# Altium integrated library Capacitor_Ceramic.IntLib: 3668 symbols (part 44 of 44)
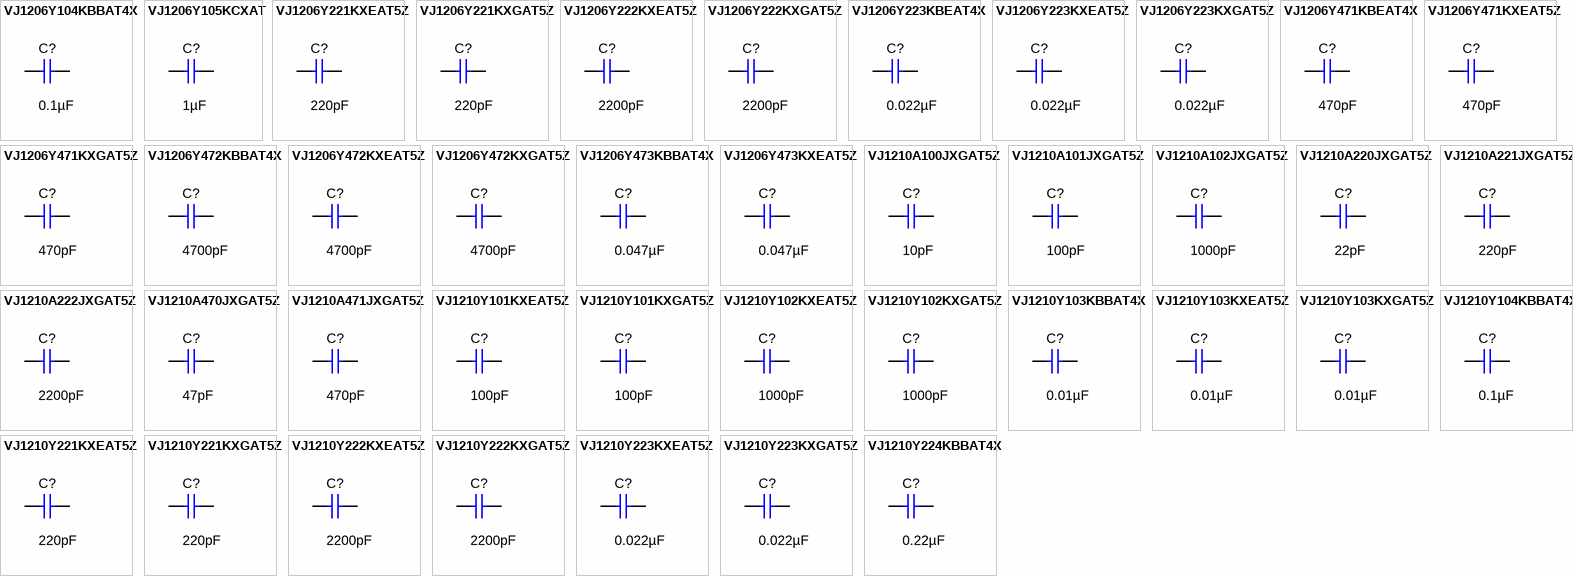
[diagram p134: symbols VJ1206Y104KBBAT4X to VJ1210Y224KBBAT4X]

## VJ1210Y104KBBAT4X
designator C?  ValueDisplayed: 0.1µF  (hidden comment: VJ1210Y104KBBAT4X)
CAP, CERM, 0.1 µF, 100 V,+/- 10%, X7R, 1210; Manufacturer: Vishay-Vitramon; Polarized: N; CompType: Capacitor; Value: 0.1uF; U/M: EA; Cap_F: 0.0000001; Tolerance_%: 10; VDC_V: 100; Value2: 100V; TaMin_C: -55; TaMax_C: 125; Cap_Case: 1210; SizeArea_mm2: 8; SizeAreaWB_mm2: 14.7; SizeX_mm: 3.2; SizeY_mm: 2.5; SizeZ_mm: 1.35; AEC Category: Q200
signal-integrity model Cap
simulation model Cap
footprint 1210
footprint 1210M
footprint 1210L
pins: 1, 2

## VJ1210Y221KXEAT5Z
designator C?  ValueDisplayed: 220pF  (hidden comment: VJ1210Y221KXEAT5Z)
CAP, CERM, 220 pF, 500 V,+/- 10%, X7R, 1210; Manufacturer: Vishay-Vitramon; Polarized: N; CompType: Capacitor; Value: 220pF; U/M: EA; Cap_F: 0.00000000022; Tolerance_%: 10; VDC_V: 500; Value2: 500V; TaMin_C: -55; TaMax_C: 125; Cap_Case: 1210; SizeArea_mm2: 8; SizeAreaWB_mm2: 14.7; SizeX_mm: 3.2; SizeY_mm: 2.5; SizeZ_mm: 1.35; AEC Category: Q200
signal-integrity model Cap
simulation model Cap
footprint 1210
footprint 1210M
footprint 1210L
pins: 1, 2

## VJ1210Y221KXGAT5Z
designator C?  ValueDisplayed: 220pF  (hidden comment: VJ1210Y221KXGAT5Z)
CAP, CERM, 220 pF, 1000 V,+/- 10%, X7R, 1210; Manufacturer: Vishay-Vitramon; Polarized: N; CompType: Capacitor; Value: 220pF; U/M: EA; Cap_F: 0.00000000022; Tolerance_%: 10; VDC_V: 1000; Value2: 1000V; TaMin_C: -55; TaMax_C: 125; Cap_Case: 1210; SizeArea_mm2: 8; SizeAreaWB_mm2: 14.7; SizeX_mm: 3.2; SizeY_mm: 2.5; SizeZ_mm: 1.35; AEC Category: Q200
signal-integrity model Cap
simulation model Cap
footprint 1210
footprint 1210M
footprint 1210L
pins: 1, 2

## VJ1210Y222KXEAT5Z
designator C?  ValueDisplayed: 2200pF  (hidden comment: VJ1210Y222KXEAT5Z)
CAP, CERM, 2200 pF, 500 V,+/- 10%, X7R, 1210; Manufacturer: Vishay-Vitramon; Polarized: N; CompType: Capacitor; Value: 2200pF; U/M: EA; Cap_F: 0.0000000022; Tolerance_%: 10; VDC_V: 500; Value2: 500V; TaMin_C: -55; TaMax_C: 125; Cap_Case: 1210; SizeArea_mm2: 8; SizeAreaWB_mm2: 14.7; SizeX_mm: 3.2; SizeY_mm: 2.5; SizeZ_mm: 1.35; AEC Category: Q200
signal-integrity model Cap
simulation model Cap
footprint 1210
footprint 1210M
footprint 1210L
pins: 1, 2

## VJ1210Y222KXGAT5Z
designator C?  ValueDisplayed: 2200pF  (hidden comment: VJ1210Y222KXGAT5Z)
CAP, CERM, 2200 pF, 1000 V,+/- 10%, X7R, 1210; Manufacturer: Vishay-Vitramon; Polarized: N; CompType: Capacitor; Value: 2200pF; U/M: EA; Cap_F: 0.0000000022; Tolerance_%: 10; VDC_V: 1000; Value2: 1000V; TaMin_C: -55; TaMax_C: 125; Cap_Case: 1210; SizeArea_mm2: 8; SizeAreaWB_mm2: 14.7; SizeX_mm: 3.2; SizeY_mm: 2.5; SizeZ_mm: 1.35; AEC Category: Q200
signal-integrity model Cap
simulation model Cap
footprint 1210
footprint 1210M
footprint 1210L
pins: 1, 2

## VJ1210Y223KXEAT5Z
designator C?  ValueDisplayed: 0.022µF  (hidden comment: VJ1210Y223KXEAT5Z)
CAP, CERM, 0.022 µF, 500 V,+/- 10%, X7R, 1210; Manufacturer: Vishay-Vitramon; Polarized: N; CompType: Capacitor; Value: 0.022uF; U/M: EA; Cap_F: 0.000000022; Tolerance_%: 10; VDC_V: 500; Value2: 500V; TaMin_C: -55; TaMax_C: 125; Cap_Case: 1210; SizeArea_mm2: 8; SizeAreaWB_mm2: 14.7; SizeX_mm: 3.2; SizeY_mm: 2.5; SizeZ_mm: 1.35; AEC Category: Q200
signal-integrity model Cap
simulation model Cap
footprint 1210
footprint 1210M
footprint 1210L
pins: 1, 2

## VJ1210Y223KXGAT5Z
designator C?  ValueDisplayed: 0.022µF  (hidden comment: VJ1210Y223KXGAT5Z)
CAP, CERM, 0.022 µF, 1000 V,+/- 10%, X7R, 1210; Manufacturer: Vishay-Vitramon; Polarized: N; CompType: Capacitor; Value: 0.022uF; U/M: EA; Cap_F: 0.000000022; Tolerance_%: 10; VDC_V: 1000; Value2: 1000V; TaMin_C: -55; TaMax_C: 125; Cap_Case: 1210; SizeArea_mm2: 8; SizeAreaWB_mm2: 14.7; SizeX_mm: 3.2; SizeY_mm: 2.5; SizeZ_mm: 1.35; AEC Category: Q200
signal-integrity model Cap
simulation model Cap
footprint 1210
footprint 1210M
footprint 1210L
pins: 1, 2

## VJ1210Y224KBBAT4X
designator C?  ValueDisplayed: 0.22µF  (hidden comment: VJ1210Y224KBBAT4X)
CAP, CERM, 0.22 µF, 100 V,+/- 10%, X7R, 1210; Manufacturer: Vishay-Vitramon; Polarized: N; CompType: Capacitor; Value: 0.22uF; U/M: EA; Cap_F: 0.00000022; Tolerance_%: 10; VDC_V: 100; Value2: 100V; TaMin_C: -55; TaMax_C: 125; Cap_Case: 1210; SizeArea_mm2: 8; SizeAreaWB_mm2: 14.7; SizeX_mm: 3.2; SizeY_mm: 2.5; SizeZ_mm: 1.35; AEC Category: Q200
signal-integrity model Cap
simulation model Cap
footprint 1210
footprint 1210M
footprint 1210L
pins: 1, 2

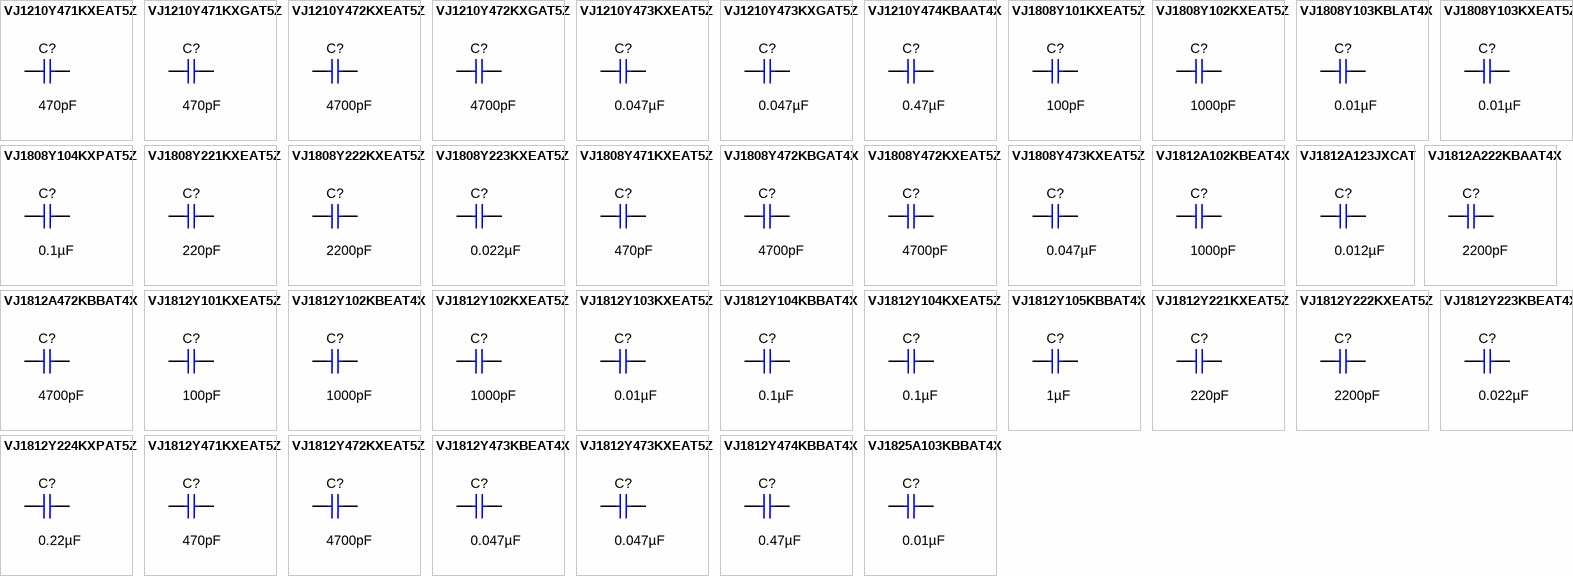
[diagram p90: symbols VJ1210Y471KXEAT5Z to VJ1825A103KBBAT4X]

## VJ1210Y471KXEAT5Z
designator C?  ValueDisplayed: 470pF  (hidden comment: VJ1210Y471KXEAT5Z)
CAP, CERM, 470 pF, 500 V,+/- 10%, X7R, 1210; Manufacturer: Vishay-Vitramon; Polarized: N; CompType: Capacitor; Value: 470pF; U/M: EA; Cap_F: 0.00000000047; Tolerance_%: 10; VDC_V: 500; Value2: 500V; TaMin_C: -55; TaMax_C: 125; Cap_Case: 1210; SizeArea_mm2: 8; SizeAreaWB_mm2: 14.7; SizeX_mm: 3.2; SizeY_mm: 2.5; SizeZ_mm: 1.35; AEC Category: Q200
signal-integrity model Cap
simulation model Cap
footprint 1210
footprint 1210M
footprint 1210L
pins: 1, 2

## VJ1210Y471KXGAT5Z
designator C?  ValueDisplayed: 470pF  (hidden comment: VJ1210Y471KXGAT5Z)
CAP, CERM, 470 pF, 1000 V,+/- 10%, X7R, 1210; Manufacturer: Vishay-Vitramon; Polarized: N; CompType: Capacitor; Value: 470pF; U/M: EA; Cap_F: 0.00000000047; Tolerance_%: 10; VDC_V: 1000; Value2: 1000V; TaMin_C: -55; TaMax_C: 125; Cap_Case: 1210; SizeArea_mm2: 8; SizeAreaWB_mm2: 14.7; SizeX_mm: 3.2; SizeY_mm: 2.5; SizeZ_mm: 1.35; AEC Category: Q200
signal-integrity model Cap
simulation model Cap
footprint 1210
footprint 1210M
footprint 1210L
pins: 1, 2

## VJ1210Y472KXEAT5Z
designator C?  ValueDisplayed: 4700pF  (hidden comment: VJ1210Y472KXEAT5Z)
CAP, CERM, 4700 pF, 500 V,+/- 10%, X7R, 1210; Manufacturer: Vishay-Vitramon; Polarized: N; CompType: Capacitor; Value: 4700pF; U/M: EA; Cap_F: 0.0000000047; Tolerance_%: 10; VDC_V: 500; Value2: 500V; TaMin_C: -55; TaMax_C: 125; Cap_Case: 1210; SizeArea_mm2: 8; SizeAreaWB_mm2: 14.7; SizeX_mm: 3.2; SizeY_mm: 2.5; SizeZ_mm: 1.35; AEC Category: Q200
signal-integrity model Cap
simulation model Cap
footprint 1210
footprint 1210M
footprint 1210L
pins: 1, 2

## VJ1210Y472KXGAT5Z
designator C?  ValueDisplayed: 4700pF  (hidden comment: VJ1210Y472KXGAT5Z)
CAP, CERM, 4700 pF, 1000 V,+/- 10%, X7R, 1210; Manufacturer: Vishay-Vitramon; Polarized: N; CompType: Capacitor; Value: 4700pF; U/M: EA; Cap_F: 0.0000000047; Tolerance_%: 10; VDC_V: 1000; Value2: 1000V; TaMin_C: -55; TaMax_C: 125; Cap_Case: 1210; SizeArea_mm2: 8; SizeAreaWB_mm2: 14.7; SizeX_mm: 3.2; SizeY_mm: 2.5; SizeZ_mm: 1.35; AEC Category: Q200
signal-integrity model Cap
simulation model Cap
footprint 1210
footprint 1210M
footprint 1210L
pins: 1, 2

## VJ1210Y473KXEAT5Z
designator C?  ValueDisplayed: 0.047µF  (hidden comment: VJ1210Y473KXEAT5Z)
CAP, CERM, 0.047 µF, 500 V,+/- 10%, X7R, 1210; Manufacturer: Vishay-Vitramon; Polarized: N; CompType: Capacitor; Value: 0.047uF; U/M: EA; Cap_F: 0.000000047; Tolerance_%: 10; VDC_V: 500; Value2: 500V; TaMin_C: -55; TaMax_C: 125; Cap_Case: 1210; SizeArea_mm2: 8; SizeAreaWB_mm2: 14.7; SizeX_mm: 3.2; SizeY_mm: 2.5; SizeZ_mm: 1.35; AEC Category: Q200
signal-integrity model Cap
simulation model Cap
footprint 1210
footprint 1210M
footprint 1210L
pins: 1, 2

## VJ1210Y473KXGAT5Z
designator C?  ValueDisplayed: 0.047µF  (hidden comment: VJ1210Y473KXGAT5Z)
CAP, CERM, 0.047 µF, 1000 V,+/- 10%, X7R, 1210; Manufacturer: Vishay-Vitramon; Polarized: N; CompType: Capacitor; Value: 0.047uF; U/M: EA; Cap_F: 0.000000047; Tolerance_%: 10; VDC_V: 1000; Value2: 1000V; TaMin_C: -55; TaMax_C: 125; Cap_Case: 1210; SizeArea_mm2: 8; SizeAreaWB_mm2: 14.7; SizeX_mm: 3.2; SizeY_mm: 2.5; SizeZ_mm: 1.35; AEC Category: Q200
signal-integrity model Cap
simulation model Cap
footprint 1210
footprint 1210M
footprint 1210L
pins: 1, 2

## VJ1210Y474KBAAT4X
designator C?  ValueDisplayed: 0.47µF  (hidden comment: VJ1210Y474KBAAT4X)
CAP, CERM, 0.47 µF, 50 V,+/- 10%, X7R, 1210; Manufacturer: Vishay-Vitramon; Polarized: N; CompType: Capacitor; Value: 0.47uF; U/M: EA; Cap_F: 0.00000047; Tolerance_%: 10; VDC_V: 50; Value2: 50V; TaMin_C: -55; TaMax_C: 125; Cap_Case: 1210; SizeArea_mm2: 8; SizeAreaWB_mm2: 14.7; SizeX_mm: 3.2; SizeY_mm: 2.5; SizeZ_mm: 1.35; AEC Category: Q200
signal-integrity model Cap
simulation model Cap
footprint 1210
footprint 1210M
footprint 1210L
pins: 1, 2

## VJ1808Y101KXEAT5Z
designator C?  ValueDisplayed: 100pF  (hidden comment: VJ1808Y101KXEAT5Z)
CAP, CERM, 100 pF, 500 V,+/- 10%, X7R, 1808; Manufacturer: Vishay-Vitramon; Polarized: N; CompType: Capacitor; Value: 100pF; U/M: EA; Cap_F: 0.0000000001; Tolerance_%: 10; VDC_V: 500; Value2: 500V; TaMin_C: -55; TaMax_C: 125; Cap_Case: 1808; SizeArea_mm2: 9; SizeAreaWB_mm2: 16.5; SizeX_mm: 4.5; SizeY_mm: 2; SizeZ_mm: 2.03; AEC Category: Q200
signal-integrity model Cap
simulation model Cap
footprint 1808
footprint 1808_M
footprint 1808_L
pins: 1, 2

## VJ1808Y102KXEAT5Z
designator C?  ValueDisplayed: 1000pF  (hidden comment: VJ1808Y102KXEAT5Z)
CAP, CERM, 1000 pF, 500 V,+/- 10%, X7R, 1808; Manufacturer: Vishay-Vitramon; Polarized: N; CompType: Capacitor; Value: 1000pF; U/M: EA; Cap_F: 0.000000001; Tolerance_%: 10; VDC_V: 500; Value2: 500V; TaMin_C: -55; TaMax_C: 125; Cap_Case: 1808; SizeArea_mm2: 9; SizeAreaWB_mm2: 16.5; SizeX_mm: 4.5; SizeY_mm: 2; SizeZ_mm: 2.03; AEC Category: Q200
signal-integrity model Cap
simulation model Cap
footprint 1808
footprint 1808_M
footprint 1808_L
pins: 1, 2

## VJ1808Y103KBLAT4X
designator C?  ValueDisplayed: 0.01µF  (hidden comment: VJ1808Y103KBLAT4X)
CAP, CERM, 0.01 µF, 630 V,+/- 10%, X7R, 1808; Manufacturer: Vishay-Vitramon; Polarized: N; CompType: Capacitor; Value: 0.01uF; U/M: EA; Cap_F: 0.00000001; Tolerance_%: 10; VDC_V: 630; Value2: 630V; TaMin_C: -55; TaMax_C: 125; Cap_Case: 1808; SizeArea_mm2: 9; SizeAreaWB_mm2: 16.5; SizeX_mm: 4.5; SizeY_mm: 2; SizeZ_mm: 2.03; AEC Category: Q200
signal-integrity model Cap
simulation model Cap
footprint 1808
footprint 1808_M
footprint 1808_L
pins: 1, 2

## VJ1808Y103KXEAT5Z
designator C?  ValueDisplayed: 0.01µF  (hidden comment: VJ1808Y103KXEAT5Z)
CAP, CERM, 0.01 µF, 500 V,+/- 10%, X7R, 1808; Manufacturer: Vishay-Vitramon; Polarized: N; CompType: Capacitor; Value: 0.01uF; U/M: EA; Cap_F: 0.00000001; Tolerance_%: 10; VDC_V: 500; Value2: 500V; TaMin_C: -55; TaMax_C: 125; Cap_Case: 1808; SizeArea_mm2: 9; SizeAreaWB_mm2: 16.5; SizeX_mm: 4.5; SizeY_mm: 2; SizeZ_mm: 2.03; AEC Category: Q200
signal-integrity model Cap
simulation model Cap
footprint 1808
footprint 1808_M
footprint 1808_L
pins: 1, 2

## VJ1808Y104KXPAT5Z
designator C?  ValueDisplayed: 0.1µF  (hidden comment: VJ1808Y104KXPAT5Z)
CAP, CERM, 0.1 µF, 250 V,+/- 10%, X7R, 1808; Manufacturer: Vishay-Vitramon; Polarized: N; CompType: Capacitor; Value: 0.1uF; U/M: EA; Cap_F: 0.0000001; Tolerance_%: 10; VDC_V: 250; Value2: 250V; TaMin_C: -55; TaMax_C: 125; Cap_Case: 1808; SizeArea_mm2: 9; SizeAreaWB_mm2: 16.5; SizeX_mm: 4.5; SizeY_mm: 2; SizeZ_mm: 2.03; AEC Category: Q200
signal-integrity model Cap
simulation model Cap
footprint 1808
footprint 1808_M
footprint 1808_L
pins: 1, 2

## VJ1808Y221KXEAT5Z
designator C?  ValueDisplayed: 220pF  (hidden comment: VJ1808Y221KXEAT5Z)
CAP, CERM, 220 pF, 500 V,+/- 10%, X7R, 1808; Manufacturer: Vishay-Vitramon; Polarized: N; CompType: Capacitor; Value: 220pF; U/M: EA; Cap_F: 0.00000000022; Tolerance_%: 10; VDC_V: 500; Value2: 500V; TaMin_C: -55; TaMax_C: 125; Cap_Case: 1808; SizeArea_mm2: 9; SizeAreaWB_mm2: 16.5; SizeX_mm: 4.5; SizeY_mm: 2; SizeZ_mm: 2.03; AEC Category: Q200
signal-integrity model Cap
simulation model Cap
footprint 1808
footprint 1808_M
footprint 1808_L
pins: 1, 2

## VJ1808Y222KXEAT5Z
designator C?  ValueDisplayed: 2200pF  (hidden comment: VJ1808Y222KXEAT5Z)
CAP, CERM, 2200 pF, 500 V,+/- 10%, X7R, 1808; Manufacturer: Vishay-Vitramon; Polarized: N; CompType: Capacitor; Value: 2200pF; U/M: EA; Cap_F: 0.0000000022; Tolerance_%: 10; VDC_V: 500; Value2: 500V; TaMin_C: -55; TaMax_C: 125; Cap_Case: 1808; SizeArea_mm2: 9; SizeAreaWB_mm2: 16.5; SizeX_mm: 4.5; SizeY_mm: 2; SizeZ_mm: 2.03; AEC Category: Q200
signal-integrity model Cap
simulation model Cap
footprint 1808
footprint 1808_M
footprint 1808_L
pins: 1, 2

## VJ1808Y223KXEAT5Z
designator C?  ValueDisplayed: 0.022µF  (hidden comment: VJ1808Y223KXEAT5Z)
CAP, CERM, 0.022 µF, 500 V,+/- 10%, X7R, 1808; Manufacturer: Vishay-Vitramon; Polarized: N; CompType: Capacitor; Value: 0.022uF; U/M: EA; Cap_F: 0.000000022; Tolerance_%: 10; VDC_V: 500; Value2: 500V; TaMin_C: -55; TaMax_C: 125; Cap_Case: 1808; SizeArea_mm2: 9; SizeAreaWB_mm2: 16.5; SizeX_mm: 4.5; SizeY_mm: 2; SizeZ_mm: 2.03; AEC Category: Q200
signal-integrity model Cap
simulation model Cap
footprint 1808
footprint 1808_M
footprint 1808_L
pins: 1, 2

## VJ1808Y471KXEAT5Z
designator C?  ValueDisplayed: 470pF  (hidden comment: VJ1808Y471KXEAT5Z)
CAP, CERM, 470 pF, 500 V,+/- 10%, X7R, 1808; Manufacturer: Vishay-Vitramon; Polarized: N; CompType: Capacitor; Value: 470pF; U/M: EA; Cap_F: 0.00000000047; Tolerance_%: 10; VDC_V: 500; Value2: 500V; TaMin_C: -55; TaMax_C: 125; Cap_Case: 1808; SizeArea_mm2: 9; SizeAreaWB_mm2: 16.5; SizeX_mm: 4.5; SizeY_mm: 2; SizeZ_mm: 2.03; AEC Category: Q200
signal-integrity model Cap
simulation model Cap
footprint 1808
footprint 1808_M
footprint 1808_L
pins: 1, 2

## VJ1808Y472KBGAT4X
designator C?  ValueDisplayed: 4700pF  (hidden comment: VJ1808Y472KBGAT4X)
CAP, CERM, 4700 pF, 1000 V,+/- 10%, X7R, 1808; Manufacturer: Vishay-Vitramon; Polarized: N; CompType: Capacitor; Value: 4700pF; U/M: EA; Cap_F: 0.0000000047; Tolerance_%: 10; VDC_V: 1000; Value2: 1000V; TaMin_C: -55; TaMax_C: 125; Cap_Case: 1808; SizeArea_mm2: 9; SizeAreaWB_mm2: 16.5; SizeX_mm: 4.5; SizeY_mm: 2; SizeZ_mm: 2.03; AEC Category: Q200
signal-integrity model Cap
simulation model Cap
footprint 1808
footprint 1808_M
footprint 1808_L
pins: 1, 2

## VJ1808Y472KXEAT5Z
designator C?  ValueDisplayed: 4700pF  (hidden comment: VJ1808Y472KXEAT5Z)
CAP, CERM, 4700 pF, 500 V,+/- 10%, X7R, 1808; Manufacturer: Vishay-Vitramon; Polarized: N; CompType: Capacitor; Value: 4700pF; U/M: EA; Cap_F: 0.0000000047; Tolerance_%: 10; VDC_V: 500; Value2: 500V; TaMin_C: -55; TaMax_C: 125; Cap_Case: 1808; SizeArea_mm2: 9; SizeAreaWB_mm2: 16.5; SizeX_mm: 4.5; SizeY_mm: 2; SizeZ_mm: 2.03; AEC Category: Q200
signal-integrity model Cap
simulation model Cap
footprint 1808
footprint 1808_M
footprint 1808_L
pins: 1, 2

## VJ1808Y473KXEAT5Z
designator C?  ValueDisplayed: 0.047µF  (hidden comment: VJ1808Y473KXEAT5Z)
CAP, CERM, 0.047 µF, 500 V,+/- 10%, X7R, 1808; Manufacturer: Vishay-Vitramon; Polarized: N; CompType: Capacitor; Value: 0.047uF; U/M: EA; Cap_F: 0.000000047; Tolerance_%: 10; VDC_V: 500; Value2: 500V; TaMin_C: -55; TaMax_C: 125; Cap_Case: 1808; SizeArea_mm2: 9; SizeAreaWB_mm2: 16.5; SizeX_mm: 4.5; SizeY_mm: 2; SizeZ_mm: 2.03; AEC Category: Q200
signal-integrity model Cap
simulation model Cap
footprint 1808
footprint 1808_M
footprint 1808_L
pins: 1, 2

## VJ1812A102KBEAT4X
designator C?  ValueDisplayed: 1000pF  (hidden comment: VJ1812A102KBEAT4X)
CAP, CERM, 1000 pF, 500 V,+/- 10%, C0G/NP0, 1812; Manufacturer: Vishay-Vitramon; Polarized: N; CompType: Capacitor; Value: 1000pF; U/M: EA; Cap_F: 0.000000001; Tolerance_%: 10; VDC_V: 500; Value2: 500V; TaMin_C: -55; TaMax_C: 125; Cap_Case: 1812; SizeArea_mm2: 14.4; SizeAreaWB_mm2: 23.1; SizeX_mm: 4.5; SizeY_mm: 3.2; SizeZ_mm: 1.35; AEC Category: Q200
signal-integrity model Cap
simulation model Cap
footprint 1812
footprint 1812M
footprint 1812L
footprint 1812_HV
pins: 1, 2

## VJ1812A123JXCAT
designator C?  ValueDisplayed: 0.012µF  (hidden comment: VJ1812A123JXCAT)
CAP, CERM, 0.012 µF, 200 V,+/- 5%, C0G/NP0, 1812; Manufacturer: Vishay-Vitramon; Polarized: N; CompType: Capacitor; Value: 0.012uF; U/M: EA; Cap_F: 0.000000012; Tolerance_%: 5; VDC_V: 200; Value2: 200V; TaMin_C: -55; TaMax_C: 125; Cap_Case: 1812; SizeArea_mm2: 14.4; SizeAreaWB_mm2: 23.1; SizeX_mm: 4.5; SizeY_mm: 3.2; SizeZ_mm: 2.54; AEC Category: Q200
signal-integrity model Cap
simulation model Cap
footprint 1812_254
pins: 1, 2

## VJ1812A222KBAAT4X
designator C?  ValueDisplayed: 2200pF  (hidden comment: VJ1812A222KBAAT4X)
CAP, CERM, 2200 pF, 50 V,+/- 10%, C0G/NP0, 1812; Manufacturer: Vishay-Vitramon; Polarized: N; CompType: Capacitor; Value: 2200pF; U/M: EA; Cap_F: 0.0000000022; Tolerance_%: 10; VDC_V: 50; Value2: 50V; TaMin_C: -55; TaMax_C: 125; Cap_Case: 1812; SizeArea_mm2: 14.4; SizeAreaWB_mm2: 23.1; SizeX_mm: 4.5; SizeY_mm: 3.2; SizeZ_mm: 1.35; AEC Category: Q200
signal-integrity model Cap
simulation model Cap
footprint 1812
footprint 1812M
footprint 1812L
footprint 1812_HV
pins: 1, 2

## VJ1812A472KBBAT4X
designator C?  ValueDisplayed: 4700pF  (hidden comment: VJ1812A472KBBAT4X)
CAP, CERM, 4700 pF, 100 V,+/- 10%, C0G/NP0, 1812; Manufacturer: Vishay-Vitramon; Polarized: N; CompType: Capacitor; Value: 4700pF; U/M: EA; Cap_F: 0.0000000047; Tolerance_%: 10; VDC_V: 100; Value2: 100V; TaMin_C: -55; TaMax_C: 125; Cap_Case: 1812; SizeArea_mm2: 14.4; SizeAreaWB_mm2: 23.1; SizeX_mm: 4.5; SizeY_mm: 3.2; SizeZ_mm: 1.35; AEC Category: Q200
signal-integrity model Cap
simulation model Cap
footprint 1812
footprint 1812M
footprint 1812L
footprint 1812_HV
pins: 1, 2

## VJ1812Y101KXEAT5Z
designator C?  ValueDisplayed: 100pF  (hidden comment: VJ1812Y101KXEAT5Z)
CAP, CERM, 100 pF, 500 V,+/- 10%, X7R, 1812; Manufacturer: Vishay-Vitramon; Polarized: N; CompType: Capacitor; Value: 100pF; U/M: EA; Cap_F: 0.0000000001; Tolerance_%: 10; VDC_V: 500; Value2: 500V; TaMin_C: -55; TaMax_C: 125; Cap_Case: 1812; SizeArea_mm2: 14.4; SizeAreaWB_mm2: 23.1; SizeX_mm: 4.5; SizeY_mm: 3.2; SizeZ_mm: 1.35; AEC Category: Q200
signal-integrity model Cap
simulation model Cap
footprint 1812
footprint 1812M
footprint 1812L
footprint 1812_HV
pins: 1, 2

## VJ1812Y102KBEAT4X
designator C?  ValueDisplayed: 1000pF  (hidden comment: VJ1812Y102KBEAT4X)
CAP, CERM, 1000 pF, 500 V,+/- 10%, X7R, 1812; Manufacturer: Vishay-Vitramon; Polarized: N; CompType: Capacitor; Value: 1000pF; U/M: EA; Cap_F: 0.000000001; Tolerance_%: 10; VDC_V: 500; Value2: 500V; TaMin_C: -55; TaMax_C: 125; Cap_Case: 1812; SizeArea_mm2: 14.4; SizeAreaWB_mm2: 23.1; SizeX_mm: 4.5; SizeY_mm: 3.2; SizeZ_mm: 1.35; AEC Category: Q200
signal-integrity model Cap
simulation model Cap
footprint 1812
footprint 1812M
footprint 1812L
footprint 1812_HV
pins: 1, 2

## VJ1812Y102KXEAT5Z
designator C?  ValueDisplayed: 1000pF  (hidden comment: VJ1812Y102KXEAT5Z)
CAP, CERM, 1000 pF, 500 V,+/- 10%, X7R, 1812; Manufacturer: Vishay-Vitramon; Polarized: N; CompType: Capacitor; Value: 1000pF; U/M: EA; Cap_F: 0.000000001; Tolerance_%: 10; VDC_V: 500; Value2: 500V; TaMin_C: -55; TaMax_C: 125; Cap_Case: 1812; SizeArea_mm2: 14.4; SizeAreaWB_mm2: 23.1; SizeX_mm: 4.5; SizeY_mm: 3.2; SizeZ_mm: 1.35; AEC Category: Q200
signal-integrity model Cap
simulation model Cap
footprint 1812
footprint 1812M
footprint 1812L
footprint 1812_HV
pins: 1, 2

## VJ1812Y103KXEAT5Z
designator C?  ValueDisplayed: 0.01µF  (hidden comment: VJ1812Y103KXEAT5Z)
CAP, CERM, 0.01 µF, 500 V,+/- 10%, X7R, 1812; Manufacturer: Vishay-Vitramon; Polarized: N; CompType: Capacitor; Value: 0.01uF; U/M: EA; Cap_F: 0.00000001; Tolerance_%: 10; VDC_V: 500; Value2: 500V; TaMin_C: -55; TaMax_C: 125; Cap_Case: 1812; SizeArea_mm2: 14.4; SizeAreaWB_mm2: 23.1; SizeX_mm: 4.5; SizeY_mm: 3.2; SizeZ_mm: 1.35; AEC Category: Q200
signal-integrity model Cap
simulation model Cap
footprint 1812
footprint 1812M
footprint 1812L
footprint 1812_HV
pins: 1, 2

## VJ1812Y104KBBAT4X
designator C?  ValueDisplayed: 0.1µF  (hidden comment: VJ1812Y104KBBAT4X)
CAP, CERM, 0.1 µF, 100 V,+/- 10%, X7R, 1812; Manufacturer: Vishay-Vitramon; Polarized: N; CompType: Capacitor; Value: 0.1uF; U/M: EA; Cap_F: 0.0000001; Tolerance_%: 10; VDC_V: 100; Value2: 100V; TaMin_C: -55; TaMax_C: 125; Cap_Case: 1812; SizeArea_mm2: 14.4; SizeAreaWB_mm2: 23.1; SizeX_mm: 4.5; SizeY_mm: 3.2; SizeZ_mm: 1.35; AEC Category: Q200
signal-integrity model Cap
simulation model Cap
footprint 1812
footprint 1812M
footprint 1812L
footprint 1812_HV
pins: 1, 2

## VJ1812Y104KXEAT5Z
designator C?  ValueDisplayed: 0.1µF  (hidden comment: VJ1812Y104KXEAT5Z)
CAP, CERM, 0.1 µF, 500 V,+/- 10%, X7R, 1812; Manufacturer: Vishay-Vitramon; Polarized: N; CompType: Capacitor; Value: 0.1uF; U/M: EA; Cap_F: 0.0000001; Tolerance_%: 10; VDC_V: 500; Value2: 500V; TaMin_C: -55; TaMax_C: 125; Cap_Case: 1812; SizeArea_mm2: 14.4; SizeAreaWB_mm2: 23.1; SizeX_mm: 4.5; SizeY_mm: 3.2; SizeZ_mm: 1.35; AEC Category: Q200
signal-integrity model Cap
simulation model Cap
footprint 1812
footprint 1812M
footprint 1812L
footprint 1812_HV
pins: 1, 2

## VJ1812Y105KBBAT4X
designator C?  ValueDisplayed: 1µF  (hidden comment: VJ1812Y105KBBAT4X)
CAP, CERM, 1 µF, 100 V,+/- 10%, X7R, 1812; Manufacturer: Vishay-Vitramon; Polarized: N; CompType: Capacitor; Value: 1uF; U/M: EA; Cap_F: 0.000001; Tolerance_%: 10; VDC_V: 100; Value2: 100V; TaMin_C: -55; TaMax_C: 125; Cap_Case: 1812; SizeArea_mm2: 14.4; SizeAreaWB_mm2: 23.1; SizeX_mm: 4.5; SizeY_mm: 3.2; SizeZ_mm: 1.35; AEC Category: Q200
signal-integrity model Cap
simulation model Cap
footprint 1812
footprint 1812M
footprint 1812L
footprint 1812_HV
pins: 1, 2

## VJ1812Y221KXEAT5Z
designator C?  ValueDisplayed: 220pF  (hidden comment: VJ1812Y221KXEAT5Z)
CAP, CERM, 220 pF, 500 V,+/- 10%, X7R, 1812; Manufacturer: Vishay-Vitramon; Polarized: N; CompType: Capacitor; Value: 220pF; U/M: EA; Cap_F: 0.00000000022; Tolerance_%: 10; VDC_V: 500; Value2: 500V; TaMin_C: -55; TaMax_C: 125; Cap_Case: 1812; SizeArea_mm2: 14.4; SizeAreaWB_mm2: 23.1; SizeX_mm: 4.5; SizeY_mm: 3.2; SizeZ_mm: 1.35; AEC Category: Q200
signal-integrity model Cap
simulation model Cap
footprint 1812
footprint 1812M
footprint 1812L
footprint 1812_HV
pins: 1, 2

## VJ1812Y222KXEAT5Z
designator C?  ValueDisplayed: 2200pF  (hidden comment: VJ1812Y222KXEAT5Z)
CAP, CERM, 2200 pF, 500 V,+/- 10%, X7R, 1812; Manufacturer: Vishay-Vitramon; Polarized: N; CompType: Capacitor; Value: 2200pF; U/M: EA; Cap_F: 0.0000000022; Tolerance_%: 10; VDC_V: 500; Value2: 500V; TaMin_C: -55; TaMax_C: 125; Cap_Case: 1812; SizeArea_mm2: 14.4; SizeAreaWB_mm2: 23.1; SizeX_mm: 4.5; SizeY_mm: 3.2; SizeZ_mm: 1.35; AEC Category: Q200
signal-integrity model Cap
simulation model Cap
footprint 1812
footprint 1812M
footprint 1812L
footprint 1812_HV
pins: 1, 2

## VJ1812Y223KBEAT4X
designator C?  ValueDisplayed: 0.022µF  (hidden comment: VJ1812Y223KBEAT4X)
CAP, CERM, 0.022 µF, 500 V,+/- 10%, X7R, 1812; Manufacturer: Vishay-Vitramon; Polarized: N; CompType: Capacitor; Value: 0.022uF; U/M: EA; Cap_F: 0.000000022; Tolerance_%: 10; VDC_V: 500; Value2: 500V; TaMin_C: -55; TaMax_C: 125; Cap_Case: 1812; SizeArea_mm2: 14.4; SizeAreaWB_mm2: 23.1; SizeX_mm: 4.5; SizeY_mm: 3.2; SizeZ_mm: 1.35; AEC Category: Q200; Green_Lifecycle: Not Set; Green_REACh: Incomplete
signal-integrity model Cap
simulation model Cap
footprint 1812
footprint 1812M
footprint 1812L
footprint 1812_HV
pins: 1, 2

## VJ1812Y224KXPAT5Z
designator C?  ValueDisplayed: 0.22µF  (hidden comment: VJ1812Y224KXPAT5Z)
CAP, CERM, 0.22 µF, 250 V,+/- 10%, X7R, 1812; Manufacturer: Vishay-Vitramon; Polarized: N; CompType: Capacitor; Value: 0.22uF; U/M: EA; Cap_F: 0.00000022; Tolerance_%: 10; VDC_V: 250; Value2: 250V; TaMin_C: -55; TaMax_C: 125; Cap_Case: 1812; SizeArea_mm2: 14.4; SizeAreaWB_mm2: 23.1; SizeX_mm: 4.5; SizeY_mm: 3.2; SizeZ_mm: 1.35; AEC Category: Q200
signal-integrity model Cap
simulation model Cap
footprint 1812
footprint 1812M
footprint 1812L
footprint 1812_HV
pins: 1, 2

## VJ1812Y471KXEAT5Z
designator C?  ValueDisplayed: 470pF  (hidden comment: VJ1812Y471KXEAT5Z)
CAP, CERM, 470 pF, 500 V,+/- 10%, X7R, 1812; Manufacturer: Vishay-Vitramon; Polarized: N; CompType: Capacitor; Value: 470pF; U/M: EA; Cap_F: 0.00000000047; Tolerance_%: 10; VDC_V: 500; Value2: 500V; TaMin_C: -55; TaMax_C: 125; Cap_Case: 1812; SizeArea_mm2: 14.4; SizeAreaWB_mm2: 23.1; SizeX_mm: 4.5; SizeY_mm: 3.2; SizeZ_mm: 1.35; AEC Category: Q200
signal-integrity model Cap
simulation model Cap
footprint 1812
footprint 1812M
footprint 1812L
footprint 1812_HV
pins: 1, 2

## VJ1812Y472KXEAT5Z
designator C?  ValueDisplayed: 4700pF  (hidden comment: VJ1812Y472KXEAT5Z)
CAP, CERM, 4700 pF, 500 V,+/- 10%, X7R, 1812; Manufacturer: Vishay-Vitramon; Polarized: N; CompType: Capacitor; Value: 4700pF; U/M: EA; Cap_F: 0.0000000047; Tolerance_%: 10; VDC_V: 500; Value2: 500V; TaMin_C: -55; TaMax_C: 125; Cap_Case: 1812; SizeArea_mm2: 14.4; SizeAreaWB_mm2: 23.1; SizeX_mm: 4.5; SizeY_mm: 3.2; SizeZ_mm: 1.35; AEC Category: Q200
signal-integrity model Cap
simulation model Cap
footprint 1812
footprint 1812M
footprint 1812L
footprint 1812_HV
pins: 1, 2

## VJ1812Y473KBEAT4X
designator C?  ValueDisplayed: 0.047µF  (hidden comment: VJ1812Y473KBEAT4X)
CAP, CERM, 0.047 µF, 500 V,+/- 10%, X7R, 1812; Manufacturer: Vishay-Vitramon; Polarized: N; CompType: Capacitor; Value: 0.047uF; U/M: EA; Cap_F: 0.000000047; Tolerance_%: 10; VDC_V: 500; Value2: 500V; TaMin_C: -55; TaMax_C: 125; Cap_Case: 1812; SizeArea_mm2: 14.4; SizeAreaWB_mm2: 23.1; SizeX_mm: 4.5; SizeY_mm: 3.2; SizeZ_mm: 1.35; AEC Category: Q200
signal-integrity model Cap
simulation model Cap
footprint 1812
footprint 1812M
footprint 1812L
footprint 1812_HV
pins: 1, 2

## VJ1812Y473KXEAT5Z
designator C?  ValueDisplayed: 0.047µF  (hidden comment: VJ1812Y473KXEAT5Z)
CAP, CERM, 0.047 µF, 500 V,+/- 10%, X7R, 1812; Manufacturer: Vishay-Vitramon; Polarized: N; CompType: Capacitor; Value: 0.047uF; U/M: EA; Cap_F: 0.000000047; Tolerance_%: 10; VDC_V: 500; Value2: 500V; TaMin_C: -55; TaMax_C: 125; Cap_Case: 1812; SizeArea_mm2: 14.4; SizeAreaWB_mm2: 23.1; SizeX_mm: 4.5; SizeY_mm: 3.2; SizeZ_mm: 1.35; AEC Category: Q200
signal-integrity model Cap
simulation model Cap
footprint 1812
footprint 1812M
footprint 1812L
footprint 1812_HV
pins: 1, 2

## VJ1812Y474KBBAT4X
designator C?  ValueDisplayed: 0.47µF  (hidden comment: VJ1812Y474KBBAT4X)
CAP, CERM, 0.47 µF, 100 V,+/- 10%, X7R, 1812; Manufacturer: Vishay-Vitramon; Polarized: N; CompType: Capacitor; Value: 0.47uF; U/M: EA; Cap_F: 0.00000047; Tolerance_%: 10; VDC_V: 100; Value2: 100V; TaMin_C: -55; TaMax_C: 125; Cap_Case: 1812; SizeArea_mm2: 14.4; SizeAreaWB_mm2: 23.1; SizeX_mm: 4.5; SizeY_mm: 3.2; SizeZ_mm: 1.35; AEC Category: Q200
signal-integrity model Cap
simulation model Cap
footprint 1812
footprint 1812M
footprint 1812L
footprint 1812_HV
pins: 1, 2

## VJ1825A103KBBAT4X
designator C?  ValueDisplayed: 0.01µF  (hidden comment: VJ1825A103KBBAT4X)
CAP, CERM, 0.01 µF, 100 V,+/- 10%, C0G/NP0, 1825; Manufacturer: Vishay-Vitramon; Polarized: N; CompType: Capacitor; Value: 0.01uF; U/M: EA; Cap_F: 0.00000001; Tolerance_%: 10; VDC_V: 100; Value2: 100V; TaMin_C: -55; TaMax_C: 125; Cap_Case: 1825; SizeArea_mm2: 28.8; SizeAreaWB_mm2: 54.6; SizeX_mm: 4.5; SizeY_mm: 6.4; SizeZ_mm: 1.1; AEC Category: Q200
signal-integrity model Cap
simulation model Cap
footprint 1825
footprint 1825_M
footprint 1825_L
pins: 1, 2

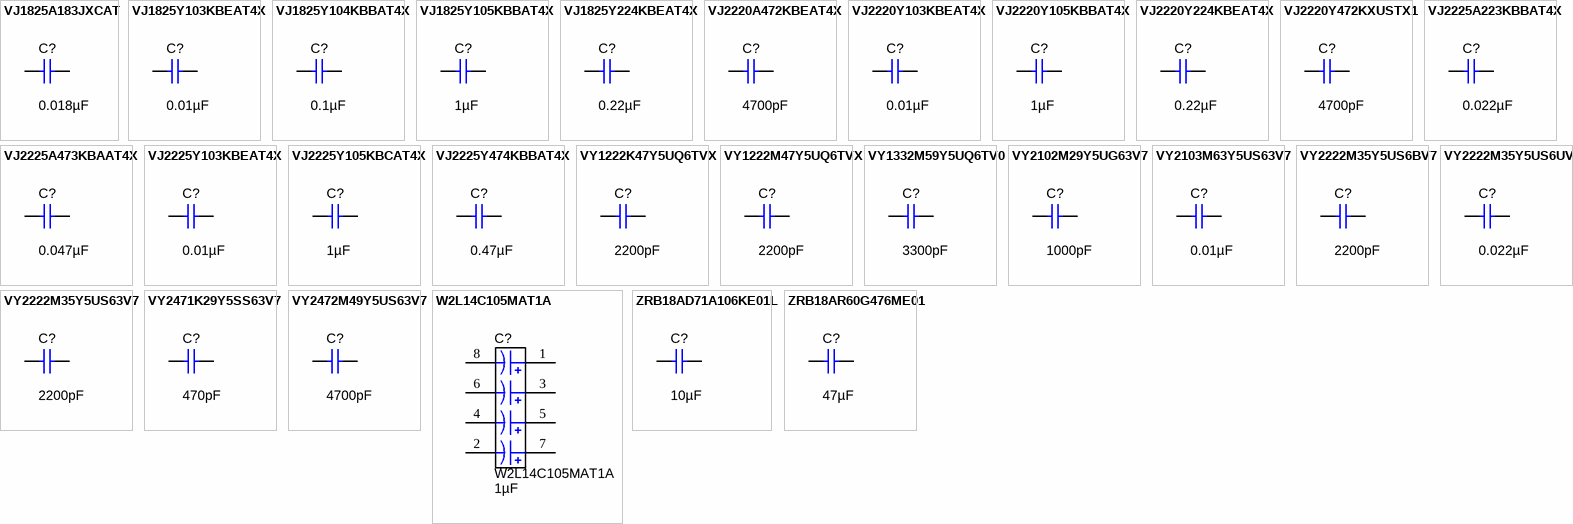
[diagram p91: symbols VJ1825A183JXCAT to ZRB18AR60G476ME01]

## VJ1825A183JXCAT
designator C?  ValueDisplayed: 0.018µF  (hidden comment: VJ1825A183JXCAT)
CAP, CERM, 0.018 µF, 200 V,+/- 5%, C0G/NP0, 1825; Manufacturer: Vishay-Vitramon; Polarized: N; CompType: Capacitor; Value: 0.018uF; U/M: EA; Cap_F: 0.000000018; Tolerance_%: 5; VDC_V: 200; Value2: 200V; TaMin_C: -55; TaMax_C: 125; Cap_Case: 1825; SizeArea_mm2: 28.8; SizeAreaWB_mm2: 54.6; SizeX_mm: 4.5; SizeY_mm: 6.4; SizeZ_mm: 2.54; AEC Category: Q200
signal-integrity model Cap
simulation model Cap
footprint 1825_254
pins: 1, 2

## VJ1825Y103KBEAT4X
designator C?  ValueDisplayed: 0.01µF  (hidden comment: VJ1825Y103KBEAT4X)
CAP, CERM, 0.01 µF, 500 V,+/- 10%, X7R, 1825; Manufacturer: Vishay-Vitramon; Polarized: N; CompType: Capacitor; Value: 0.01uF; U/M: EA; Cap_F: 0.00000001; Tolerance_%: 10; VDC_V: 500; Value2: 500V; TaMin_C: -55; TaMax_C: 125; Cap_Case: 1825; SizeArea_mm2: 28.8; SizeAreaWB_mm2: 54.6; SizeX_mm: 4.5; SizeY_mm: 6.4; SizeZ_mm: 1.1; AEC Category: Q200
signal-integrity model Cap
simulation model Cap
footprint 1825
footprint 1825_M
footprint 1825_L
pins: 1, 2

## VJ1825Y104KBBAT4X
designator C?  ValueDisplayed: 0.1µF  (hidden comment: VJ1825Y104KBBAT4X)
CAP, CERM, 0.1 µF, 100 V,+/- 10%, X7R, 1825; Manufacturer: Vishay-Vitramon; Polarized: N; CompType: Capacitor; Value: 0.1uF; U/M: EA; Cap_F: 0.0000001; Tolerance_%: 10; VDC_V: 100; Value2: 100V; TaMin_C: -55; TaMax_C: 125; Cap_Case: 1825; SizeArea_mm2: 28.8; SizeAreaWB_mm2: 54.6; SizeX_mm: 4.5; SizeY_mm: 6.4; SizeZ_mm: 1.1; AEC Category: Q200
signal-integrity model Cap
simulation model Cap
footprint 1825
footprint 1825_M
footprint 1825_L
pins: 1, 2

## VJ1825Y105KBBAT4X
designator C?  ValueDisplayed: 1µF  (hidden comment: VJ1825Y105KBBAT4X)
CAP, CERM, 1 µF, 100 V,+/- 10%, X7R, 1825; Manufacturer: Vishay-Vitramon; Polarized: N; CompType: Capacitor; Value: 1uF; U/M: EA; Cap_F: 0.000001; Tolerance_%: 10; VDC_V: 100; Value2: 100V; TaMin_C: -55; TaMax_C: 125; Cap_Case: 1825; SizeArea_mm2: 28.8; SizeAreaWB_mm2: 54.6; SizeX_mm: 4.5; SizeY_mm: 6.4; SizeZ_mm: 1.1; AEC Category: Q200
signal-integrity model Cap
simulation model Cap
footprint 1825
footprint 1825_M
footprint 1825_L
pins: 1, 2

## VJ1825Y224KBEAT4X
designator C?  ValueDisplayed: 0.22µF  (hidden comment: VJ1825Y224KBEAT4X)
CAP, CERM, 0.22 µF, 500 V,+/- 10%, X7R, 1825; Manufacturer: Vishay-Vitramon; Polarized: N; CompType: Capacitor; Value: 0.22uF; U/M: EA; Cap_F: 0.00000022; Tolerance_%: 10; VDC_V: 500; Value2: 500V; TaMin_C: -55; TaMax_C: 125; Cap_Case: 1825; SizeArea_mm2: 28.8; SizeAreaWB_mm2: 54.6; SizeX_mm: 4.5; SizeY_mm: 6.4; SizeZ_mm: 1.1; AEC Category: Q200
signal-integrity model Cap
simulation model Cap
footprint 1825
footprint 1825_M
footprint 1825_L
pins: 1, 2

## VJ2220A472KBEAT4X
designator C?  ValueDisplayed: 4700pF  (hidden comment: VJ2220A472KBEAT4X)
CAP, CERM, 4700 pF, 500 V,+/- 10%, C0G/NP0, 2220; Manufacturer: Vishay-Vitramon; Polarized: N; CompType: Capacitor; Value: 4700pF; U/M: EA; Cap_F: 0.0000000047; Tolerance_%: 10; VDC_V: 500; Value2: 500V; TaMin_C: -55; TaMax_C: 125; Cap_Case: 2220; SizeArea_mm2: 28.5; SizeAreaWB_mm2: 53.9; SizeX_mm: 5.7; SizeY_mm: 5; SizeZ_mm: 2.2; AEC Category: Q200
signal-integrity model Cap
simulation model Cap
footprint 2220_220
footprint 2220_220M
footprint 2220_220L
pins: 1, 2

## VJ2220Y103KBEAT4X
designator C?  ValueDisplayed: 0.01µF  (hidden comment: VJ2220Y103KBEAT4X)
CAP, CERM, 0.01 µF, 500 V,+/- 10%, X7R, 2220; Manufacturer: Vishay-Vitramon; Polarized: N; CompType: Capacitor; Value: 0.01uF; U/M: EA; Cap_F: 0.00000001; Tolerance_%: 10; VDC_V: 500; Value2: 500V; TaMin_C: -55; TaMax_C: 125; Cap_Case: 2220; SizeArea_mm2: 28.5; SizeAreaWB_mm2: 53.9; SizeX_mm: 5.7; SizeY_mm: 5; SizeZ_mm: 2.2; AEC Category: Q200
signal-integrity model Cap
simulation model Cap
footprint 2220_220
footprint 2220_220M
footprint 2220_220L
pins: 1, 2

## VJ2220Y105KBBAT4X
designator C?  ValueDisplayed: 1µF  (hidden comment: VJ2220Y105KBBAT4X)
CAP, CERM, 1 µF, 100 V,+/- 10%, X7R, 2220; Manufacturer: Vishay-Vitramon; Polarized: N; CompType: Capacitor; Value: 1uF; U/M: EA; Cap_F: 0.000001; Tolerance_%: 10; VDC_V: 100; Value2: 100V; TaMin_C: -55; TaMax_C: 125; Cap_Case: 2220; SizeArea_mm2: 28.5; SizeAreaWB_mm2: 53.9; SizeX_mm: 5.7; SizeY_mm: 5; SizeZ_mm: 2.2; AEC Category: Q200
signal-integrity model Cap
simulation model Cap
footprint 2220_220
footprint 2220_220M
footprint 2220_220L
pins: 1, 2

## VJ2220Y224KBEAT4X
designator C?  ValueDisplayed: 0.22µF  (hidden comment: VJ2220Y224KBEAT4X)
CAP, CERM, 0.22 µF, 500 V,+/- 10%, X7R, 2220; Manufacturer: Vishay-Vitramon; Polarized: N; CompType: Capacitor; Value: 0.22uF; U/M: EA; Cap_F: 0.00000022; Tolerance_%: 10; VDC_V: 500; Value2: 500V; TaMin_C: -55; TaMax_C: 125; Cap_Case: 2220; SizeArea_mm2: 28.5; SizeAreaWB_mm2: 53.9; SizeX_mm: 5.7; SizeY_mm: 5; SizeZ_mm: 2.2; AEC Category: Q200
signal-integrity model Cap
simulation model Cap
footprint 2220_220
footprint 2220_220M
footprint 2220_220L
pins: 1, 2

## VJ2220Y472KXUSTX1
designator C?  ValueDisplayed: 4700pF  (hidden comment: VJ2220Y472KXUSTX1)
CAP, CERM, 4700 pF, 250 V,+/- 10%, X7R, 2220; Manufacturer: Vishay-Vitramon; Polarized: N; CompType: Capacitor; Value: 4700pF; U/M: EA; Cap_F: 0.0000000047; Tolerance_%: 10; VDC_V: 250; Value2: 250V; TaMin_C: -55; TaMax_C: 125; Cap_Case: 2220; SizeArea_mm2: 28.5; SizeAreaWB_mm2: 53.9; SizeX_mm: 5.7; SizeY_mm: 5; SizeZ_mm: 2.2; AEC Category: Q200
signal-integrity model Cap
simulation model Cap
footprint 2220_220
footprint 2220_220M
footprint 2220_220L
pins: 1, 2

## VJ2225A223KBBAT4X
designator C?  ValueDisplayed: 0.022µF  (hidden comment: VJ2225A223KBBAT4X)
CAP, CERM, 0.022 µF, 100 V,+/- 10%, C0G/NP0, 2225; Manufacturer: Vishay-Vitramon; Polarized: N; CompType: Capacitor; Value: 0.022uF; U/M: EA; Cap_F: 0.000000022; Tolerance_%: 10; VDC_V: 100; Value2: 100V; TaMin_C: -55; TaMax_C: 125; Cap_Case: 2225; SizeArea_mm2: 35.91; SizeAreaWB_mm2: 63.91; SizeX_mm: 5.7; SizeY_mm: 6.3; SizeZ_mm: 2; AEC Category: Q200
signal-integrity model Cap
simulation model Cap
footprint 2225
footprint 2225_M
footprint 2225_L
pins: 1, 2

## VJ2225A473KBAAT4X
designator C?  ValueDisplayed: 0.047µF  (hidden comment: VJ2225A473KBAAT4X)
CAP, CERM, 0.047 µF, 50 V,+/- 10%, C0G/NP0, 2225; Manufacturer: Vishay-Vitramon; Polarized: N; CompType: Capacitor; Value: 0.047uF; U/M: EA; Cap_F: 0.000000047; Tolerance_%: 10; VDC_V: 50; Value2: 50V; TaMin_C: -55; TaMax_C: 125; Cap_Case: 2225; SizeArea_mm2: 35.91; SizeAreaWB_mm2: 63.91; SizeX_mm: 5.7; SizeY_mm: 6.3; SizeZ_mm: 2; AEC Category: Q200
signal-integrity model Cap
simulation model Cap
footprint 2225
footprint 2225_M
footprint 2225_L
pins: 1, 2

## VJ2225Y103KBEAT4X
designator C?  ValueDisplayed: 0.01µF  (hidden comment: VJ2225Y103KBEAT4X)
CAP, CERM, 0.01 µF, 500 V,+/- 10%, X7R, 2225; Manufacturer: Vishay-Vitramon; Polarized: N; CompType: Capacitor; Value: 0.01uF; U/M: EA; Cap_F: 0.00000001; Tolerance_%: 10; VDC_V: 500; Value2: 500V; TaMin_C: -55; TaMax_C: 125; Cap_Case: 2225; SizeArea_mm2: 35.91; SizeAreaWB_mm2: 63.91; SizeX_mm: 5.7; SizeY_mm: 6.3; SizeZ_mm: 2; AEC Category: Q200
signal-integrity model Cap
simulation model Cap
footprint 2225
footprint 2225_M
footprint 2225_L
pins: 1, 2

## VJ2225Y105KBCAT4X
designator C?  ValueDisplayed: 1µF  (hidden comment: VJ2225Y105KBCAT4X)
CAP, CERM, 1 µF, 200 V,+/- 10%, X7R, 2225; Manufacturer: Vishay-Vitramon; Polarized: N; CompType: Capacitor; Value: 1uF; U/M: EA; Cap_F: 0.000001; Tolerance_%: 10; VDC_V: 200; Value2: 200V; TaMin_C: -55; TaMax_C: 125; Cap_Case: 2225; SizeArea_mm2: 35.91; SizeAreaWB_mm2: 63.91; SizeX_mm: 5.7; SizeY_mm: 6.3; SizeZ_mm: 2; AEC Category: Q200
signal-integrity model Cap
simulation model Cap
footprint 2225
footprint 2225_M
footprint 2225_L
pins: 1, 2

## VJ2225Y474KBBAT4X
designator C?  ValueDisplayed: 0.47µF  (hidden comment: VJ2225Y474KBBAT4X)
CAP, CERM, 0.47 µF, 100 V,+/- 10%, X7R, 2225; Manufacturer: Vishay-Vitramon; Polarized: N; CompType: Capacitor; Value: 0.47uF; U/M: EA; Cap_F: 0.00000047; Tolerance_%: 10; VDC_V: 100; Value2: 100V; TaMin_C: -55; TaMax_C: 125; Cap_Case: 2225; SizeArea_mm2: 35.91; SizeAreaWB_mm2: 63.91; SizeX_mm: 5.7; SizeY_mm: 6.3; SizeZ_mm: 2; AEC Category: Q200
signal-integrity model Cap
simulation model Cap
footprint 2225
footprint 2225_M
footprint 2225_L
pins: 1, 2

## VY1222K47Y5UQ6TVX
designator C?  ValueDisplayed: 2200pF  (hidden comment: VY1222K47Y5UQ6TVX)
CAP, CERM, 2200 pF, X1 760 VAC/Y1 500 VAC, +/- 10%, Y5U, D12xT5mm; Manufacturer: Vishay-Bccomponents; Polarized: N; CompType: Capacitor; Value: 2200pF; U/M: EA; Cap_F: 0.0000000022; Tolerance_%: 10; TaMin_C: -40; TaMax_C: 125; Cap_Case: 12x5mm; SizeArea_mm2: 60; SizeAreaWB_mm2: 98; SizeX_mm: 12; SizeY_mm: 5; SizeZ_mm: 16; AEC Category: Q200; AC_Safety: X1Y1; VAC_X: 760; VAC_Y: 500
signal-integrity model Cap
simulation model Cap
footprint VY1_1200x500_V
pins: 1, 2

## VY1222M47Y5UQ6TVX
designator C?  ValueDisplayed: 2200pF  (hidden comment: VY1222M47Y5UQ6TVX)
CAP, CERM, 2200 pF, X1 760 VAC/Y1 500 VAC, +/- 20%, Y5U, D12xT5mm; Manufacturer: Vishay-Bccomponents; Polarized: N; CompType: Capacitor; Value: 2200pF; U/M: EA; Cap_F: 0.0000000022; Tolerance_%: 20; TaMin_C: -40; TaMax_C: 125; Cap_Case: 12x5mm; SizeArea_mm2: 60; SizeAreaWB_mm2: 98; SizeX_mm: 12; SizeY_mm: 5; SizeZ_mm: 16; AEC Category: Q200; AC_Safety: X1Y1; VAC_X: 760; VAC_Y: 500
signal-integrity model Cap
simulation model Cap
footprint VY1_1200x500_V
pins: 1, 2

## VY1332M59Y5UQ6TV0
designator C?  ValueDisplayed: 3300pF  (hidden comment: VY1332M59Y5UQ6TV0)
CAP, CERM, 3300 pF, X1 760 VAC/Y1 500 VAC, +/- 20%, Y5U, D15xT5mm; Manufacturer: Vishay-Bccomponents; Polarized: N; CompType: Capacitor; Value: 3300pF; U/M: EA; Cap_F: 0.0000000033; Tolerance_%: 20; TaMin_C: -40; TaMax_C: 125; Cap_Case: 15x5mm; SizeArea_mm2: 75; SizeAreaWB_mm2: 119; SizeX_mm: 15; SizeY_mm: 5; SizeZ_mm: 19; AEC Category: Q200; AC_Safety: X1Y1; VAC_X: 760; VAC_Y: 500
signal-integrity model Cap
simulation model Cap
footprint VY1_1500x500
pins: 1, 2

## VY2102M29Y5UG63V7
designator C?  ValueDisplayed: 1000pF  (hidden comment: VY2102M29Y5UG63V7)
CAP, CERM, 1000 pF, X1 440 VAC/Y2 300 VAC, +/- 20%, Y5U, Radial Disc 7.5mm, ls=7.5; Manufacturer: Vishay-Bccomponents; Polarized: N; CompType: Capacitor; Value: 1000pF; U/M: EA; Cap_F: 0.000000001; Tolerance_%: 20; TaMin_C: -40; TaMax_C: 125; SizeArea_mm2: 41.5; SizeAreaWB_mm2: 72.1; SizeX_mm: 8.3; SizeY_mm: 5; SizeZ_mm: 11.5; AEC Category: Q200; AC_Safety: X1Y2; VAC_X: 440; VAC_Y: 300
signal-integrity model Cap
simulation model Cap
footprint CAPRD750W60D750H1050
pins: 1, 2

## VY2103M63Y5US63V7
designator C?  ValueDisplayed: 0.01µF  (hidden comment: VY2103M63Y5US63V7)
CAP, CERM, 0.01 µF, X1 440 VAC/Y2 300 VAC, +/- 20%, Y5U, D16xT5mm; Manufacturer: Vishay-Bccomponents; Polarized: N; CompType: Capacitor; Value: 0.01uF; U/M: EA; Cap_F: 0.00000001; Tolerance_%: 20; TaMin_C: -40; TaMax_C: 125; Cap_Case: 16x5mm; SizeArea_mm2: 80; SizeAreaWB_mm2: 126; SizeX_mm: 16; SizeY_mm: 5; AEC Category: Q200; Green_Lifecycle: Not Set; Green_REACh: Incomplete; AC_Safety: X1Y2; VAC_X: 440; VAC_Y: 300
signal-integrity model Cap
simulation model Cap
footprint VY2_1600x500
pins: 1, 2

## VY2222M35Y5US6BV7
designator C?  ValueDisplayed: 2200pF  (hidden comment: VY2222M35Y5US6BV7)
CAP, CERM, 2200 pF, X1 440 VAC/Y2 300 VAC, +/- 20%, Y5U, D9xT5mm; Manufacturer: Vishay-Bccomponents; Polarized: N; CompType: Capacitor; Value: 2200pF; U/M: EA; Cap_F: 0.0000000022; Tolerance_%: 20; TaMin_C: -40; TaMax_C: 125; Cap_Case: 9x5mm; SizeArea_mm2: 45; SizeAreaWB_mm2: 77; SizeX_mm: 9; SizeY_mm: 5; SizeZ_mm: 13; AEC Category: Q200; AC_Safety: X1Y2; VAC_X: 440; VAC_Y: 300
signal-integrity model Cap
simulation model Cap
footprint VY2_900x500
pins: 1, 2

## VY2222M35Y5US6UV5
designator C?  ValueDisplayed: 0.022µF  (hidden comment: VY2222M35Y5US6UV5)
CAP, CERM, 0.022 µF, X1 440 VAC/Y2 300 VAC, +/- 20%, Y5U, CAPRD500W60D900H1200; Manufacturer: Vishay-Bccomponents; Polarized: N; CompType: Capacitor; Value: 0.022uF; U/M: EA; Cap_F: 0.000000022; Tolerance_%: 20; TaMin_C: -40; TaMax_C: 125; Cap_Case: Radial Disc 9mm, ls=10; SizeArea_mm2: 45; SizeAreaWB_mm2: 77; SizeX_mm: 9; SizeY_mm: 5; SizeZ_mm: 13; AEC Category: Q200; AC_Safety: X1Y2; VAC_X: 440; VAC_Y: 300
signal-integrity model Cap
simulation model Cap
footprint CAPRD500W60D900H1200
pins: 1, 2

## VY2222M35Y5US63V7
designator C?  ValueDisplayed: 2200pF  (hidden comment: VY2222M35Y5US63V7)
CAP, CERM, 2200 pF, X1 440 VAC/Y2 300 VAC, +/- 20%, Y5U, D9xT5mm; Manufacturer: Vishay-Bccomponents; Polarized: N; CompType: Capacitor; Value: 2200pF; U/M: EA; Cap_F: 0.0000000022; Tolerance_%: 20; TaMin_C: -40; TaMax_C: 125; Cap_Case: 9x5mm; SizeArea_mm2: 45; SizeAreaWB_mm2: 77; SizeX_mm: 9; SizeY_mm: 5; SizeZ_mm: 13; AEC Category: Q200; AC_Safety: X1Y2; VAC_X: 440; VAC_Y: 300
signal-integrity model Cap
simulation model Cap
footprint VY2_900x500
pins: 1, 2

## VY2471K29Y5SS63V7
designator C?  ValueDisplayed: 470pF  (hidden comment: VY2471K29Y5SS63V7)
CAP, CERM, 470 pF, X1 440 VAC/Y2 300 VAC, +/- 10%, Y5S, 5x7.5 mm; Manufacturer: Vishay-Bccomponents; Polarized: N; CompType: Capacitor; Value: 470pF; U/M: EA; Cap_F: 0.00000000047; Tolerance_%: 10; TaMin_C: -40; TaMax_C: 125; Cap_Case: Disk, 5x7.5 mm; SizeArea_mm2: 37.5; SizeAreaWB_mm2: 66.5; SizeX_mm: 7.5; SizeY_mm: 5; SizeZ_mm: 10.5; AEC Category: Q200; AC_Safety: X1Y2; VAC_X: 440; VAC_Y: 300
signal-integrity model Cap
simulation model Cap
footprint VY2_750x500
pins: 1, 2

## VY2472M49Y5US63V7
designator C?  ValueDisplayed: 4700pF  (hidden comment: VY2472M49Y5US63V7)
CAP, CERM, 4700 pF, X1 440 VAC/Y2 300 VAC, +/- 20%, Y5U, TH, 12.5x5mm; Manufacturer: Vishay-Bccomponents; Polarized: N; CompType: Capacitor; Value: 4700pF; U/M: EA; Cap_F: 0.0000000047; Tolerance_%: 20; TaMin_C: -40; TaMax_C: 125; Cap_Case: 12.5x5x16.5; SizeArea_mm2: 62.5; SizeAreaWB_mm2: 101.5; SizeX_mm: 12.5; SizeY_mm: 5; SizeZ_mm: 17.5; AEC Category: Q200; AC_Safety: X1Y2; VAC_X: 440; VAC_Y: 300
signal-integrity model Cap
simulation model Cap
footprint VY2_1250x500x1650
pins: 1, 2

## W2L14C105MAT1A
designator C?  ValueDisplayed: 1µF
CAP, CERM, 1 µF, 4 V,+/- 20%, X7R, 2.03x1.27mm; Manufacturer: AVX; SymbolCreator: Altium; CompType: Capacitor; U/M: EA; Cap_F: 0.000001; Value: 1uF; Tolerance_%: 20; VDC_V: 4; Value2: 4V; TaMin_C: -55; TaMax_C: 125; Polarized: Y; Cap_Case: 2.03x1.27x0.95mm; SizeArea_mm2: 2.5781; SizeAreaWB_mm2: 6.8781; SizeX_mm: 2.03; SizeY_mm: 1.27; SizeZ_mm: 0.95; AEC Category: Q200; AEC Qualified: N
footprint IDC_0508
pins: 1, 2, 3, 4, 5, 6, 7, 8

## ZRB18AD71A106KE01L
designator C?  ValueDisplayed: 10µF  (hidden comment: ZRB18AD71A106KE01L)
CAP, CERM, 10 µF, 10 V,+/- 10%, X7T, 0603; Manufacturer: MuRata; Polarized: N; CompType: Capacitor; Value: 10uF; U/M: EA; Cap_F: 0.00001; Tolerance_%: 10; Value2: 10V; TaMin_C: -55; TaMax_C: 125; Cap_Case: 0603; SizeArea_mm2: 1.28; SizeAreaWB_mm2: 4.68; SizeX_mm: 1.6; SizeY_mm: 0.8; SizeZ_mm: 1.2; AEC Category: Q200; Green_Lifecycle: Not Set; Green_REACh: Incomplete
signal-integrity model Cap
simulation model Cap
footprint 0603_120
pins: 1, 2

## ZRB18AR60G476ME01
designator C?  ValueDisplayed: 47µF  (hidden comment: ZRB18AR60G476ME01)
CAP, CERM, 47 µF, 4 V,+/- 20%, X5R, 0603; Manufacturer: MuRata; Polarized: N; CompType: Capacitor; Value: 47uF; U/M: EA; Cap_F: 0.000047; Tolerance_%: 20; VDC_V: 4; Value2: 4V; TaMin_C: -55; TaMax_C: 85; Cap_Case: 0603; SizeArea_mm2: 1.28; SizeAreaWB_mm2: 4.68; SizeX_mm: 1.6; SizeY_mm: 0.8; SizeZ_mm: 1.2; AEC Category: Q200
signal-integrity model Cap
simulation model Cap
footprint 0603_120
pins: 1, 2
